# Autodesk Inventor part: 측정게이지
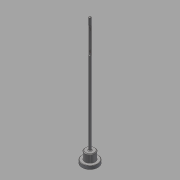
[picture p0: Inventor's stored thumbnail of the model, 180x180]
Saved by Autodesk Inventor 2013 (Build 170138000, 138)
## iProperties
Created: 2017-05
Part Number: 측정게이지
Material: 스테인리스강
Document SubType Name: Modeling
Designer: mduedu
Density: 8.08 g/cm^3
Mass: 36.8413 g
Surface Area: 29.7093 cm^2
Volume: 4.55957 cm^3
Author: mduedu
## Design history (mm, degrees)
sketch "스케치1"
  geometry: C1 r 11 at (0, 0); 1 further point
  constraints: 1 centre point, 1 coincident
  dimensions: "d0" = 22 diameter of C1
extrude "돌출1" new body sketch "스케치1" distance "d2" = 5; taper "d3" = 0 deg
sketch "스케치2"
  geometry: C1 r 7 at (0, 0); 1 further point
  constraints: 1 centre point, 1 coincident
  dimensions: "d4" = 14 diameter of C1
extrude "돌출2" join sketch "스케치2" distance "d5" = 11; taper "d6" = 0 deg
sketch "스케치3"
  geometry: C1 r 1.5 at (0, 0); 1 further point
  constraints: 1 centre point, 1 coincident
  dimensions: "d7" = 3 diameter of C1
extrude "돌출3" join sketch "스케치3" distance "d8" = 160; taper "d9" = 0 deg
fillet "모깎기1" dims "d10" = 1
chamfer "모따기1" distance "d11" = 1; stored, may be unused: second distance "d12" = 2, angle "d13" = 45 deg
sketch "스케치4"
  geometry: L1 (15, 7)-(16, 6) reference; L2 (5, 7)-(15, 7) reference; L3 (15, -7)-(5, -7) reference; L4 (16, -6)-(15, -7) reference; L5 (16, 6)-(16, 2.5) reference; L6 (17, 1.5)-(175, 1.5) reference; L7 (175, 1.5)-(176, 0.5) reference; L8 (176, 0.5)-(176, -0.5) reference; L9 (176, -0.5)-(175, -1.5) reference; L10 (175, -1.5)-(17, -1.5) reference; L11 (16, -2.5)-(16, -6) reference; L12 (176, 0)-(0, 0); L13 (166, 0)-(130, 0); L14 (130, 0)-(130, 1.5); L15 (130, 1.5)-(166, 1.5); L16 (166, 1.5)-(166, 0); L17 (0, 11)-(5, 11) reference; L18 (5, 11)-(5, 7) reference; L19 (5, -7)-(5, -11) reference; L20 (5, -11)-(0, -11) reference; L21 (0, -11)-(0, 11) reference; A1 r 1 centre (17, 2.5) between (16, 2.5) and (17, 1.5) reference; A2 r 1 centre (17, -2.5) between (17, -1.5) and (16, -2.5) reference
  constraints: 10 end point, 2 parallel, 2 point on line, 1 horizontal, 1 midpoint, 1 perpendicular
  dimensions: "d14" = 10 distance from line of L16 L7.end; "d15" = 36 distance between parallel lines of L14 L16
extrude "돌출4" cut sketch "스케치4" stored distance "d16" = 160; taper "d17" = 0 deg
sketch "스케치5"
  geometry: L1 (0, 0)-(3, 0) reference; L2 (3, 36)-(0, 36) reference; L3 (1.5, 0)-(1.5, 36); 3 further points
  constraints: 2 end point, 2 midpoint, 2 point on line, 2 other
  dimensions: "d18" = 5 distance from line of point (1.5, 5) L1; "d19" = 5 distance from line of point (1.5, 31) L2
feature "엠보싱1" sketch "스케치5" dims "d20" = 0.3, "d21" = 0
chamfer "모따기2" distance "d32" = 0.5; stored, may be unused: second distance "d33" = 2, angle "d34" = 45 deg
node "솔리드1"
node "절단 모서리 투영1"
